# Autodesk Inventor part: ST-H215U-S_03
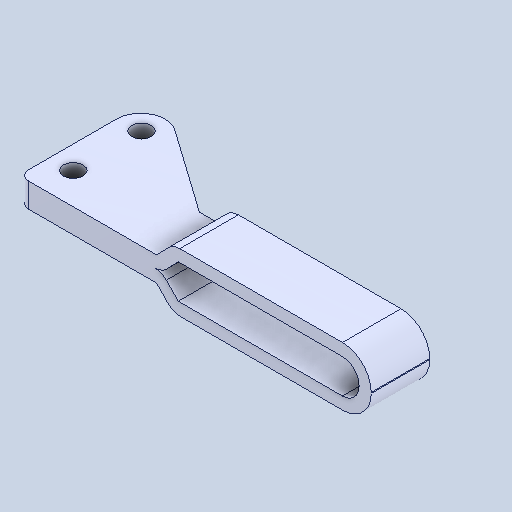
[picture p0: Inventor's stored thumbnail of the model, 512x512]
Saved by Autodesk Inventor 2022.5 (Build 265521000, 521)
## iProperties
Created: 2024-07
Part Number: ST-H215U-S_03
Material: 一般
Document SubType Name: Modeling
Designer: ImaoCorp
Density: 1 g/cm^3
Appearance: 既定
Author: ImaoCorp
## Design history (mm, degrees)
feature "ST-H215U-S_03"
node "ソリッド1"
